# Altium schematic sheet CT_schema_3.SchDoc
size 316 x 200 mm
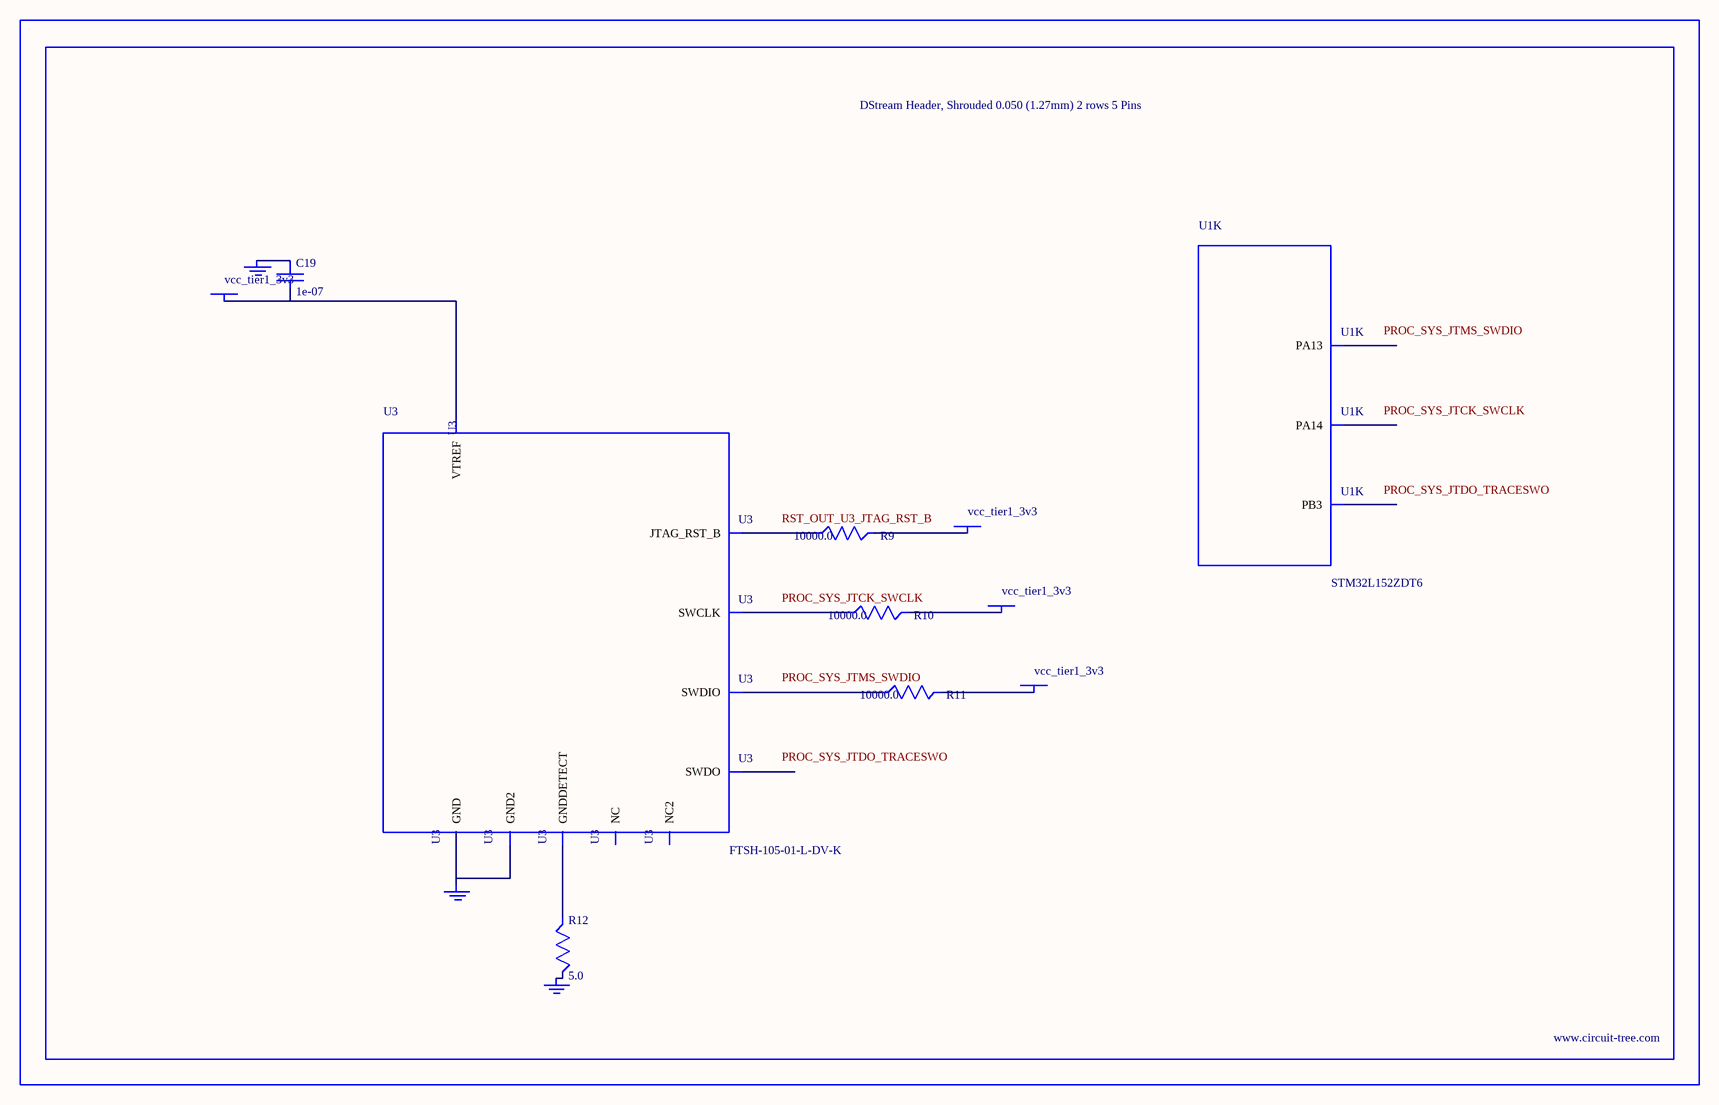
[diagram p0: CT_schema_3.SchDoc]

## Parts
BORDER2  (no value)
C19  1e-07  [C0402]
GND_INSTANCE_2_0  (no value)
GND_INSTANCE_2_1  (no value)
GND_INSTANCE_2_2  (no value)
POWER_INSTANCE_2_0  vcc_tier1_3v3
POWER_INSTANCE_2_1  vcc_tier1_3v3
POWER_INSTANCE_2_2  vcc_tier1_3v3
POWER_INSTANCE_2_3  vcc_tier1_3v3
R9  10000.0  [R0603]
R10  10000.0  [R0603]
R11  10000.0  [R0603]
R12  5.0  [R0603]
U1  STM32L152ZDT6  [LQFP144]  (part K of 12)
U3  FTSH-105-01-L-DV-K  [SAMTEC_FTSH-105-01-L-DV-K]

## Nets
NetC19_1: C19.1 GND_INSTANCE_2_0.0(GND)
NetC19_2: C19.2 POWER_INSTANCE_2_0.0(PWR) U3.1(VTREF)
NetGND_INSTANCE_2_1_0: GND_INSTANCE_2_1.0(GND) R12.2
NetGND_INSTANCE_2_2_0: GND_INSTANCE_2_2.0(GND) U3.3(GND) U3.5(GND2)
NetPOWER_INSTANCE_2_1_0: POWER_INSTANCE_2_1.0(PWR) R11.2
NetPOWER_INSTANCE_2_2_0: POWER_INSTANCE_2_2.0(PWR) R10.2
NetPOWER_INSTANCE_2_3_0: POWER_INSTANCE_2_3.0(PWR) R9.2
NetR9_1: R9.1 U3.10(JTAG_RST_B)
NetR10_1: R10.1 U3.4(SWCLK)
NetR11_1: R11.1 U3.2(SWDIO)
NetR12_1: R12.1 U3.9(GNDDETECT)

Not connected (* = marked no-connect by the designer): U1 105(PA13) 109(PA14) 133(PB3); U3 6(SWDO) 7(NC) 8(NC2)

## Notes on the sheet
- Labels drawn without touching a wire or pin: PROC_SYS_JTCK_SWCLK, PROC_SYS_JTDO_TRACESWO, PROC_SYS_JTMS_SWDIO, RST_OUT_U3_JTAG_RST_B

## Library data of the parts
BORDER2 = BORDER_PAGE2
C19 = C0402C104K3RACTU
GND_INSTANCE_2_0-GND_INSTANCE_2_2 = GND
POWER_INSTANCE_2_0-POWER_INSTANCE_2_3 = PWR
R9-R11 = RC0603JR-0710KL
R12 = ERJ-3GEYJ5R1V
